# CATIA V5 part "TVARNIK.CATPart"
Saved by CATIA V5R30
Part number: TVARNIK
Bounding box of the stored display mesh (mm): x -70 to 70, y -69.99 to 69.99, z -16.275 to 57.272
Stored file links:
  C:\Users\ondra\Desktop\PŘÍLOHA P III\CATIA\TVARNIK.CATPart
  C:\Users\ondra\Desktop\FORMA_BAKALARKA\Part1.CATPart
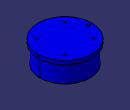
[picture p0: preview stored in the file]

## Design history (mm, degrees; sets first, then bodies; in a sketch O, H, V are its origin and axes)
Body1 (main body)
  Body2 "TVARNIK"
    Solid1: linked copy from another document
  Assemble1: tool Body2
  DatumPoint1
  Plane1: type Offset, RefPlane yz-plane, Offset 70, reversed
  DatumPoint2
  Sketch1 on face of Solid1, origin (51.9537, 0, 57.2718), H (1, 0, 0), V (0, 1, 0)
    point P1 (0, 0)
    reference projected point E1 (0, 0) from vertex of DatumPoint1
    coincidence: E1 P1
  Sketch2 on face of Solid1, origin (36.7368, 36.7368, 57.2718), H (1, 0, 0), V (0, 1, 0)
    point P1 (0, 0)
    reference projected point E1 (0, 0) from vertex of DatumPoint2
    coincidence: E1 P1
  Hole1: placed by Sketch2, at (36.7368, 36.7368, 57.2718) direction (0, 0, -1), diameter 6, through (limit type 6)
  Sketch3, origin (-88.524, 0, 154.2715), H (1, 0, 0), V (0, 1, 0), geometry linked from another document
  Sketch4, origin (-88.524, 0, 154.2715), H (-1, 0, 0), V (0, -1, 0), geometry linked from another document
  UserPattern1: of Hole1, copies 8, at the points of Sketch3
  DatumSurface1
  DatumSurface2
  Sketch5 on face of Solid1, origin (0, 0, 57.2718), H (1, 0, 0), V (0, 1, 0)
    reference projected curve E2 from face of DatumSurface2
    point P1 (-61.024, 0)
    concentricity: P1 E2
  Sketch6 on face of Solid1, origin (-61.024, 0, 57.2718), H (1, 0, 0), V (0, 1, 0)
    point P1 (0, 0)
    reference projected point E1 (0, 0) from Sketch5.P1
    coincidence: E1 P1
  Hole2: placed by Sketch6, at (-61.024, 0, 57.2718) direction (0, 0, -1), diameter 5.5, through (limit type 6), counterbore diameter 8.5, counterbore depth 8
  Plane2: type Offset, RefPlane yz-plane, Offset 65, reversed
  DatumCurve1
  Plane3: stored without definition
  Sketch7 on Plane2, origin (-65, 0, 0), H (0, 1, 0), V (0, 0, 1)
    line L1 (5, 1.2715) -> (-5, 1.2715)
    line L2 (-5, 1.2715) -> (-5, 23.2715)
    line L3 (-5, 23.2715) -> (5, 23.2715)
    line L4 (5, 23.2715) -> (5, 1.2715)
    length L3 = 10
    length L2 = 22
    horizontal: L1 H, L3 H
    vertical: L2 V, L4 V
  Pocket1: profile Sketch7, direction (1, 0, 0), length 14
  Plane4: stored without definition
  Sketch8 on Plane3, origin (70, 0, 0), H (0, 1, 0), V (0, 0, 1)
    construction circle A1 centre (0, 53.0718) radius 2.408
    point P1 (0, 53.0718)
    reference projected line E1 (70, 57.2718) -> (-70, 57.2718) from edge [face of Solid1 | face of Solid1]
    point P2 (0, 53.0718)
    distance E1 P1 = 4.2
    coincidence: P1 V, P2 P1
  Sketch9 on Plane4, origin (70, 0, 53.0718), H (0, 1, 0), V (0, 0, 1)
    point P1 (0, 0)
    reference projected point E1 (0, 0) from Sketch8.P2
    coincidence: E1 P1
  Hole3: placed by Sketch9, at (70, 0, 53.0718) direction (-1, 0, 0), diameter 5, depth 7, V-bottom angle 120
